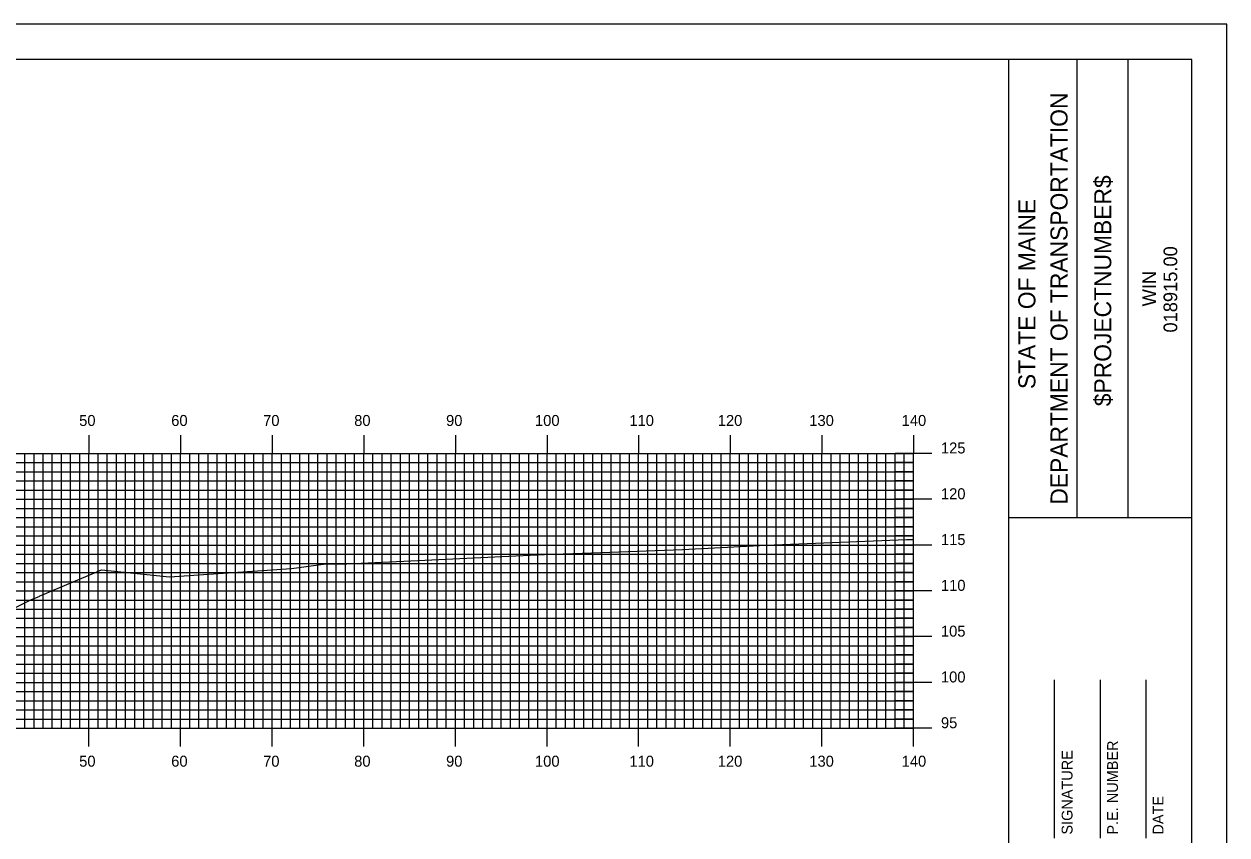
# Model space of a CAD drawing. Extents: x 1684405 to 1684749, y 461260 to 461480.
# Drawn here: x 1684614.1 to 1684745.4, y 461391.4 to 461480 of the extents above; entities that cross this region are included whole.
import ezdxf

# ---------------------------------------------------------------- set-up
doc = ezdxf.new("R2010")
doc.units = 0
for name, color, linetype in [('BORDER', 7, 'Continuous'), ('H_V ANNOTATION', 7, 'Continuous'), ('MAJOR', 7, 'Continuous'), ('MINOR', 7, 'Continuous'), ('PLOT BOUNDARY', 7, 'Continuous'), ('S_Roadway_Centerline', 7, 'Continuous')]:
    doc.layers.add(name, color=color, linetype=linetype)

msp = doc.modelspace()

# ---------------------------------------------------------------- linework, layer by layer
at = {"layer": 'BORDER'}
for p, q in [((1684721.6, 461266.07), (1684721.6, 461476.07)), ((1684729.06, 461426.07), (1684729.06, 461476.07)), ((1684734.65, 461426.07), (1684734.65, 461476.07)), ((1684721.61, 461426.06), (1684741.6, 461426.06)), ((1684726.6, 461391.08), (1684726.6, 461408.37)), ((1684731.6, 461391.08), (1684731.6, 461408.37)), ((1684736.6, 461391.08), (1684736.6, 461408.37))]:
    msp.add_line(p, q, dxfattribs=at)
msp.add_lwpolyline([(1684421.6, 461266.07), (1684741.6, 461266.07), (1684741.6, 461476.07), (1684421.6, 461476.07)], close=True, dxfattribs=at)
at = {"layer": 'MAJOR'}
for p, q in [((1684621.2, 461435.08), (1684621.2, 461433.07)), ((1684631.2, 461435.08), (1684631.2, 461433.07)), ((1684641.2, 461435.08), (1684641.2, 461433.07)), ((1684651.2, 461435.08), (1684651.2, 461433.07)), ((1684661.2, 461435.08), (1684661.2, 461433.07)), ((1684671.2, 461435.08), (1684671.2, 461433.07)), ((1684681.2, 461435.08), (1684681.2, 461433.07)), ((1684691.2, 461435.08), (1684691.2, 461433.07)), ((1684701.2, 461435.08), (1684701.2, 461433.07)), ((1684711.2, 461435.08), (1684711.2, 461433.07)), ((1684431.2, 461433.07), (1684711.2, 461433.07)), ((1684431.2, 461433.07), (1684711.2, 461433.07)), ((1684621.2, 461403.07), (1684621.2, 461433.07)), ((1684631.2, 461403.07), (1684631.2, 461433.07)), ((1684641.2, 461403.07), (1684641.2, 461433.07)), ((1684651.2, 461403.07), (1684651.2, 461433.07)), ((1684661.2, 461403.07), (1684661.2, 461433.07)), ((1684671.2, 461403.07), (1684671.2, 461433.07)), ((1684681.2, 461403.07), (1684681.2, 461433.07)), ((1684691.2, 461403.07), (1684691.2, 461433.07)), ((1684701.2, 461403.07), (1684701.2, 461433.07)), ((1684713.21, 461433.07), (1684709.2, 461433.07)), ((1684711.2, 461403.07), (1684711.2, 461433.07)), ((1684711.2, 461403.07), (1684711.2, 461433.07)), ((1684431.2, 461428.07), (1684711.2, 461428.07)), ((1684713.21, 461428.07), (1684709.2, 461428.07)), ((1684431.2, 461423.07), (1684711.2, 461423.07)), ((1684713.21, 461423.07), (1684709.2, 461423.07)), ((1684431.2, 461418.07), (1684711.2, 461418.07)), ((1684713.21, 461418.07), (1684709.2, 461418.07)), ((1684431.2, 461413.07), (1684711.2, 461413.07)), ((1684713.21, 461413.07), (1684709.2, 461413.07)), ((1684431.2, 461408.07), (1684711.2, 461408.07)), ((1684713.21, 461408.07), (1684709.2, 461408.07)), ((1684431.2, 461403.07), (1684711.2, 461403.07)), ((1684431.2, 461403.07), (1684711.2, 461403.07)), ((1684621.2, 461401.07), (1684621.2, 461403.07)), ((1684631.2, 461401.07), (1684631.2, 461403.07)), ((1684641.2, 461401.07), (1684641.2, 461403.07)), ((1684651.2, 461401.07), (1684651.2, 461403.07)), ((1684661.2, 461401.07), (1684661.2, 461403.07)), ((1684671.2, 461401.07), (1684671.2, 461403.07)), ((1684681.2, 461401.07), (1684681.2, 461403.07)), ((1684691.2, 461401.07), (1684691.2, 461403.07)), ((1684701.2, 461401.07), (1684701.2, 461403.07)), ((1684713.21, 461403.07), (1684709.2, 461403.07)), ((1684711.2, 461401.07), (1684711.2, 461403.07))]:
    msp.add_line(p, q, dxfattribs=at)
at = {"layer": 'MINOR'}
for p, q in [((1684614.2, 461403.07), (1684614.2, 461433.07)), ((1684615.2, 461403.07), (1684615.2, 461433.07)), ((1684616.2, 461403.07), (1684616.2, 461433.07)), ((1684617.2, 461403.07), (1684617.2, 461433.07)), ((1684618.2, 461403.07), (1684618.2, 461433.07)), ((1684619.2, 461403.07), (1684619.2, 461433.07)), ((1684620.2, 461403.07), (1684620.2, 461433.07)), ((1684622.2, 461403.07), (1684622.2, 461433.07)), ((1684623.2, 461403.07), (1684623.2, 461433.07)), ((1684624.2, 461403.07), (1684624.2, 461433.07)), ((1684625.2, 461403.07), (1684625.2, 461433.07)), ((1684626.2, 461403.07), (1684626.2, 461433.07)), ((1684627.2, 461403.07), (1684627.2, 461433.07)), ((1684628.2, 461403.07), (1684628.2, 461433.07)), ((1684629.2, 461403.07), (1684629.2, 461433.07)), ((1684630.2, 461403.07), (1684630.2, 461433.07)), ((1684632.2, 461403.07), (1684632.2, 461433.07)), ((1684633.2, 461403.07), (1684633.2, 461433.07)), ((1684634.2, 461403.07), (1684634.2, 461433.07)), ((1684635.2, 461403.07), (1684635.2, 461433.07)), ((1684636.2, 461403.07), (1684636.2, 461433.07)), ((1684637.2, 461403.07), (1684637.2, 461433.07)), ((1684638.2, 461403.07), (1684638.2, 461433.07)), ((1684639.2, 461403.07), (1684639.2, 461433.07)), ((1684640.2, 461403.07), (1684640.2, 461433.07)), ((1684642.2, 461403.07), (1684642.2, 461433.07)), ((1684643.2, 461403.07), (1684643.2, 461433.07)), ((1684644.2, 461403.07), (1684644.2, 461433.07)), ((1684645.2, 461403.07), (1684645.2, 461433.07)), ((1684646.2, 461403.07), (1684646.2, 461433.07)), ((1684647.2, 461403.07), (1684647.2, 461433.07)), ((1684648.2, 461403.07), (1684648.2, 461433.07)), ((1684649.2, 461403.07), (1684649.2, 461433.07)), ((1684650.2, 461403.07), (1684650.2, 461433.07)), ((1684652.2, 461403.07), (1684652.2, 461433.07)), ((1684653.2, 461403.07), (1684653.2, 461433.07)), ((1684654.2, 461403.07), (1684654.2, 461433.07)), ((1684655.2, 461403.07), (1684655.2, 461433.07)), ((1684656.2, 461403.07), (1684656.2, 461433.07)), ((1684657.2, 461403.07), (1684657.2, 461433.07)), ((1684658.2, 461403.07), (1684658.2, 461433.07)), ((1684659.2, 461403.07), (1684659.2, 461433.07)), ((1684660.2, 461403.07), (1684660.2, 461433.07)), ((1684662.2, 461403.07), (1684662.2, 461433.07)), ((1684663.2, 461403.07), (1684663.2, 461433.07)), ((1684664.2, 461403.07), (1684664.2, 461433.07)), ((1684665.2, 461403.07), (1684665.2, 461433.07)), ((1684666.2, 461403.07), (1684666.2, 461433.07)), ((1684667.2, 461403.07), (1684667.2, 461433.07)), ((1684668.2, 461403.07), (1684668.2, 461433.07)), ((1684669.2, 461403.07), (1684669.2, 461433.07)), ((1684670.2, 461403.07), (1684670.2, 461433.07)), ((1684672.2, 461403.07), (1684672.2, 461433.07)), ((1684673.2, 461403.07), (1684673.2, 461433.07)), ((1684674.2, 461403.07), (1684674.2, 461433.07)), ((1684675.2, 461403.07), (1684675.2, 461433.07)), ((1684676.2, 461403.07), (1684676.2, 461433.07)), ((1684677.2, 461403.07), (1684677.2, 461433.07)), ((1684678.2, 461403.07), (1684678.2, 461433.07)), ((1684679.2, 461403.07), (1684679.2, 461433.07)), ((1684680.2, 461403.07), (1684680.2, 461433.07)), ((1684682.2, 461403.07), (1684682.2, 461433.07)), ((1684683.2, 461403.07), (1684683.2, 461433.07)), ((1684684.2, 461403.07), (1684684.2, 461433.07)), ((1684685.2, 461403.07), (1684685.2, 461433.07)), ((1684686.2, 461403.07), (1684686.2, 461433.07)), ((1684687.2, 461403.07), (1684687.2, 461433.07)), ((1684688.2, 461403.07), (1684688.2, 461433.07)), ((1684689.2, 461403.07), (1684689.2, 461433.07)), ((1684690.2, 461403.07), (1684690.2, 461433.07)), ((1684692.2, 461403.07), (1684692.2, 461433.07)), ((1684693.2, 461403.07), (1684693.2, 461433.07)), ((1684694.2, 461403.07), (1684694.2, 461433.07)), ((1684695.2, 461403.07), (1684695.2, 461433.07)), ((1684696.2, 461403.07), (1684696.2, 461433.07)), ((1684697.2, 461403.07), (1684697.2, 461433.07)), ((1684698.2, 461403.07), (1684698.2, 461433.07)), ((1684699.2, 461403.07), (1684699.2, 461433.07)), ((1684700.2, 461403.07), (1684700.2, 461433.07)), ((1684702.2, 461403.07), (1684702.2, 461433.07)), ((1684703.2, 461403.07), (1684703.2, 461433.07)), ((1684704.2, 461403.07), (1684704.2, 461433.07)), ((1684705.2, 461403.07), (1684705.2, 461433.07)), ((1684706.2, 461403.07), (1684706.2, 461433.07)), ((1684707.2, 461403.07), (1684707.2, 461433.07)), ((1684708.2, 461403.07), (1684708.2, 461433.07)), ((1684709.2, 461403.07), (1684709.2, 461433.07)), ((1684710.2, 461403.07), (1684710.2, 461433.07)), ((1684431.2, 461432.07), (1684711.2, 461432.07)), ((1684431.2, 461431.07), (1684711.2, 461431.07)), ((1684711.2, 461432.07), (1684709.2, 461432.07)), ((1684711.2, 461431.07), (1684709.2, 461431.07)), ((1684431.2, 461430.07), (1684711.2, 461430.07)), ((1684711.2, 461430.07), (1684709.2, 461430.07)), ((1684431.2, 461429.07), (1684711.2, 461429.07)), ((1684711.2, 461429.07), (1684709.2, 461429.07)), ((1684431.2, 461427.07), (1684711.2, 461427.07)), ((1684711.2, 461427.07), (1684709.2, 461427.07)), ((1684431.2, 461426.07), (1684711.2, 461426.07)), ((1684711.2, 461426.07), (1684709.2, 461426.07)), ((1684431.2, 461425.07), (1684711.2, 461425.07)), ((1684711.2, 461425.07), (1684709.2, 461425.07)), ((1684431.2, 461424.07), (1684711.2, 461424.07)), ((1684711.2, 461424.07), (1684709.2, 461424.07)), ((1684431.2, 461422.07), (1684711.2, 461422.07)), ((1684711.2, 461422.07), (1684709.2, 461422.07)), ((1684431.2, 461421.07), (1684711.2, 461421.07)), ((1684711.2, 461421.07), (1684709.2, 461421.07)), ((1684431.2, 461420.07), (1684711.2, 461420.07)), ((1684431.2, 461419.07), (1684711.2, 461419.07)), ((1684711.2, 461420.07), (1684709.2, 461420.07)), ((1684711.2, 461419.07), (1684709.2, 461419.07)), ((1684431.2, 461417.07), (1684711.2, 461417.07)), ((1684711.2, 461417.07), (1684709.2, 461417.07)), ((1684431.2, 461416.07), (1684711.2, 461416.07)), ((1684431.2, 461415.07), (1684711.2, 461415.07)), ((1684711.2, 461416.07), (1684709.2, 461416.07)), ((1684711.2, 461415.07), (1684709.2, 461415.07)), ((1684431.2, 461414.07), (1684711.2, 461414.07)), ((1684711.2, 461414.07), (1684709.2, 461414.07)), ((1684431.2, 461412.07), (1684711.2, 461412.07)), ((1684711.2, 461412.07), (1684709.2, 461412.07)), ((1684431.2, 461411.07), (1684711.2, 461411.07)), ((1684431.2, 461410.07), (1684711.2, 461410.07)), ((1684711.2, 461411.07), (1684709.2, 461411.07)), ((1684711.2, 461410.07), (1684709.2, 461410.07)), ((1684431.2, 461409.07), (1684711.2, 461409.07)), ((1684711.2, 461409.07), (1684709.2, 461409.07)), ((1684431.2, 461407.07), (1684711.2, 461407.07)), ((1684431.2, 461406.07), (1684711.2, 461406.07)), ((1684711.2, 461407.07), (1684709.2, 461407.07)), ((1684711.2, 461406.07), (1684709.2, 461406.07)), ((1684431.2, 461405.07), (1684711.2, 461405.07)), ((1684711.2, 461405.07), (1684709.2, 461405.07)), ((1684431.2, 461404.07), (1684711.2, 461404.07)), ((1684711.2, 461404.07), (1684709.2, 461404.07))]:
    msp.add_line(p, q, dxfattribs=at)
at = {"layer": 'PLOT BOUNDARY'}
msp.add_lwpolyline([(1684405.42, 461259.95), (1684745.42, 461259.95), (1684745.42, 461479.95), (1684405.42, 461479.95)], close=True, dxfattribs=at)
at = {"layer": 'S_Roadway_Centerline'}
for points in [[(1684622.55, 461420.36), (1684629.99, 461419.61), (1684643.3, 461420.52), (1684647.07, 461421.02), (1684649.35, 461421.02), (1684656.32, 461421.33), (1684667.04, 461421.86), (1684670.91, 461422.04), (1684677.06, 461422.26), (1684686, 461422.6), (1684695.08, 461423.06), (1684710.45, 461423.66), (1684711.2, 461423.69)], [(1684581.38, 461422.44), (1684584.16, 461421.64), (1684584.59, 461421.56), (1684588.79, 461420.53), (1684592.74, 461419.56), (1684596.85, 461418.55), (1684599.04, 461418.01), (1684602.78, 461417.09), (1684606.27, 461416.24), (1684606.29, 461416.23), (1684606.31, 461416.23), (1684608.38, 461415.7), (1684608.58, 461415.66), (1684610.81, 461415.09), (1684614.84, 461417.09), (1684615.66, 461417.43), (1684615.75, 461417.47), (1684615.85, 461417.51), (1684616.31, 461417.71), (1684617.16, 461418.07), (1684621.8, 461420.03), (1684622.55, 461420.36)]]:
    msp.add_lwpolyline(points, dxfattribs=at)

# ---------------------------------------------------------------- texts
at = {"layer": 'BORDER'}
for s, height, p in [('DEPARTMENT OF TRANSPORTATION', 1.8635, (1684728.02, 461427.48)), ('$PROJECTNUMBER$', 1.8635, (1684732.79, 461438.23)), ('STATE OF MAINE', 1.8635, (1684724.51, 461440.1)), ('018915.00', 1.491, (1684739.99, 461446.27)), ('WIN', 1.491, (1684737.68, 461449.13)), ('P.E. NUMBER', 1.1811, (1684733.52, 461391.46)), ('SIGNATURE', 1.181, (1684728.56, 461391.46)), ('DATE', 1.181, (1684738.49, 461391.46))]:
    msp.add_text(s, height=height, rotation=90, dxfattribs=at).set_placement(p)
at = {"layer": 'H_V ANNOTATION'}
for s, p in [('50', (1684620.13, 461436.07)), ('60', (1684630.18, 461436.07)), ('70', (1684640.21, 461436.07)), ('80', (1684650.15, 461436.07)), ('90', (1684660.18, 461436.07)), ('100', (1684669.89, 461436.07)), ('110', (1684680.19, 461436.07)), ('120', (1684689.84, 461436.07)), ('130', (1684699.83, 461436.07)), ('140', (1684709.91, 461436.07)), ('125', (1684714.2, 461433.07)), ('120', (1684714.2, 461428.07)), ('115', (1684714.2, 461423.07)), ('110', (1684714.2, 461418.07)), ('105', (1684714.2, 461413.07)), ('100', (1684714.2, 461408.07)), ('95', (1684714.2, 461403.07)), ('50', (1684620.13, 461398.87)), ('60', (1684630.18, 461398.87)), ('70', (1684640.21, 461398.87)), ('80', (1684650.15, 461398.87)), ('90', (1684660.18, 461398.87)), ('100', (1684669.89, 461398.87)), ('110', (1684680.19, 461398.87)), ('120', (1684689.84, 461398.87)), ('130', (1684699.83, 461398.87)), ('140', (1684709.91, 461398.87))]:
    msp.add_text(s, height=1.2, dxfattribs=at).set_placement(p)

doc.saveas('drawing.dxf')
